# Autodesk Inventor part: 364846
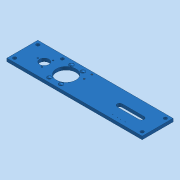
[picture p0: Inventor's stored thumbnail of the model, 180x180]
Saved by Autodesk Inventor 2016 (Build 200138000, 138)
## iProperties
Company: Mayer & Müller AG Schaltgeräte
Created: 2006-07
Part Number: 364846
Material: 1.0120
Document SubType Name: Modeling
Designer: I.Baliuc
Manufacturer: Standard
Standards Organization: Custom
Description: Seitenteil, Trenner
Density: 7.85 g/cm^3
Appearance: RAL 5012 Lichtblau
HalbzeugNorm: DIN 174
Zweck: Antriebseite: Motor-Standard
Abmessung: Fl. 120x12-525
Author: T.Messerschmitt
Keywords: 380125
Revision Number: 364846
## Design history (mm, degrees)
sketch "Skizze2"
  geometry: L1 (-170, 60)-(355, 60); L2 (355, 60)-(355, -60); L3 (355, -60)-(-170, -60); L4 (-170, -60)-(-170, 60); L5 (-222.5, 0)-(512.5, 0) reference; L6 (0, -72)-(0, 96) reference; L7 (292.5, 10)-(207.5, 10); L8 (207.5, -10)-(292.5, -10); C1 r 38 at (0, 0); A1 r 10 centre (292.5, 0) between (292.5, -10) and (292.5, 10); A2 r 10 centre (207.5, 0) between (207.5, 10) and (207.5, -10)
  constraints: 12 end point, 4 point on circle, 4 point on line, 3 centre point, 3 parallel, 2 tangent, 1 horizontal, 1 perpendicular, 2 other
  dimensions: "d4" = 170 distance between parallel lines of L4 L6; "d5" = 525 distance of L1.start L1.end; "d6" = 120 distance of L3.end L1.start; "d7" = 76 diameter of C1; "d8" = 85 distance of A2.centre A1.centre; "d9" = 20 distance between parallel lines of L7 L8; "d10" = 62.5 distance from line of L2 A1.centre
extrude "Extrusion2" new body sketch "Skizze2" distance "d11" = 12; taper "d12" = 0 deg
sketch "Skizze3"
  geometry: L1 (355, 60)-(355, -60) reference; L2 (-170, -60)-(-170, 60) reference; L3 (-222.5, 0)-(512.5, 0) reference; 4 further points
  constraints: 2 symmetric about line
  dimensions: "d13" = 90 distance of point (-155, -45) point (-155, 45); "d14" = 15 distance from line of point (-155, 45) L2; "d15" = 90 distance of point (340, -45) point (340, 45) (= d13); "d16" = 15 distance from line of point (340, 45) L1 (= d14)
hole "Bohrung_Ø13" sketch "Skizze3" at (-155, 45), (-155, -45), (340, -45), (340, 45) diameter "d17" = 13; stored, may be unused: countersink angle "d21" = 90 deg, drill point angle "d23" = 118 deg; dims "d18" = 6, "d19" = 4, "d20" = 2, "d22" = 8
sketch "Skizze4"
  geometry: L1 (-222.5, 0)-(512.5, 0) reference; L2 (0, -72)-(0, 96) reference; 4 further points
  constraints: 3 symmetric about line
  dimensions: "d24" = 85 distance of point (22.5, -42.5) point (22.5, 42.5); "d25" = 45 distance of point (-22.5, 42.5) point (22.5, 42.5)
hole "Bohrung2" sketch "Skizze4" at (22.5, 42.5), (22.5, -42.5), (-22.5, -42.5), (-22.5, 42.5) diameter "d26" = 16.5; stored, may be unused: countersink angle "d30" = 90 deg, drill point angle "d32" = 0 deg; dims "d27" = 6, "d28" = 16.5, "d29" = 0.4, "d31" = 0.7
sketch "Skizze5"
  geometry: C1 r 8.25 at (0, 0) reference; C2 r 8.25 at (0, -85) reference; C3 r 8.25 at (45, -85) reference; C4 r 8.25 at (45, 0) reference; 4 further points
  constraints: 4 coincident
hole "Bohrung3" sketch "Skizze5" at (0, 0), (45, 0), (45, -85), (0, -85) diameter "d33" = 8.4; stored, may be unused: countersink angle "d37" = 90 deg, drill point angle "d39" = 118 deg; dims "d34" = 6, "d35" = 16.5 (= d26), "d36" = 2, "d38" = 8
sketch "Skizze6" dims "d56" = 10
  geometry: L1 (-170, -60)-(-170, 60) reference; L2 (-222.5, 0)-(512.5, 0) reference; C1 r 38 at (0, 0) reference; 2 further points
  constraints: 1 vertical, 1 other
  dimensions: "d49" = 50 horizontal distance of point (50, 20) C1.centre; "d50" = 20 vertical distance of C1.centre point (50, 20); "d53" = 30 distance of point (50, 20) point (50, 50)
hole "Bohrung_M8" sketch "Skizze6" at (50, 20), (50, 50) diameter "d42" = 6.647; stored, may be unused: countersink angle "d46" = 90 deg, drill point angle "d48" = 118 deg; dims "d43" = 6, "d44" = 4, "d45" = 2, "d47" = 8
sketch "Skizze7"
  geometry: L1 (0, -72)-(0, 96) reference; L2 (-222.5, 0)-(512.5, 0) reference; 1 further point
  constraints: 1 point on line
  dimensions: "d58" = 85 distance from line of L1 point (-85, 0)
hole "Bohrung_Ø36" sketch "Skizze7" at (-85, 0) diameter "d59" = 36; stored, may be unused: countersink angle "d63" = 90 deg, drill point angle "d65" = 118 deg; dims "d60" = 6, "d61" = 4, "d62" = 2, "d64" = 8
sketch "Skizze8"
  geometry: L1 (-222.5, 0)-(512.5, 0) reference; C1 r 18 at (-85, 0) reference; 3 further points
  constraints: 1 point on line, 4 other
  dimensions: "d66" = 25 distance of point (-110, 0) C1.centre; "d69" = 360 deg dimension on C1.centre point (-110, 0) (derived)
hole "Bohrung_Ø5.5" sketch "Skizze8" at (-110, 0), (-72.5, -21.651), (-72.5, 21.651) diameter "d71" = 5.5; stored, may be unused: countersink angle "d75" = 90 deg, drill point angle "d77" = 118 deg; dims "d72" = 6, "d73" = 4, "d74" = 2, "d76" = 8
sketch "Skizze9"
  geometry: C1 r 18 at (-85, 0) reference; 1 further point
  dimensions: "d78" = 25 horizontal distance of point (-60, 45) C1.centre; "d79" = 45 vertical distance of C1.centre point (-60, 45)
hole "Bohrung_Ø12" sketch "Skizze9" at (-60, 45) diameter "d80" = 12; stored, may be unused: countersink angle "d84" = 90 deg, drill point angle "d86" = 118 deg; dims "d81" = 6, "d82" = 4, "d83" = 2, "d85" = 8
sketch "Skizze10" dims "d96" = 10
  geometry: L1 (355, 60)-(355, -60) reference; L2 (355, -60)-(-170, -60) reference; 4 further points
  constraints: 1 horizontal, 2 other
  dimensions: "d87" = 15 distance from line of L2 point (274, -45); "d88" = 81 distance from line of point (274, -45) L1; "d89" = 30 distance of point (274, -45) point (244, -45); "d90" = 15 distance from line of L2 point (244, -45) (= d87); "d93" = 18 distance of point (274, -45) point (256, -45)
hole "Bohrung_Ø2" sketch "Skizze10" at (274, -45), (244, -45), (256, -45), (226, -45) diameter "d98" = 2; stored, may be unused: countersink angle "d102" = 90 deg, drill point angle "d104" = 118 deg; dims "d99" = 6, "d100" = 4, "d101" = 2, "d103" = 8
node "Volumenkörper1"
node "Volumenkörpern"
node "Oberflächenkörpern"
node "Projizierte Kontur1"
